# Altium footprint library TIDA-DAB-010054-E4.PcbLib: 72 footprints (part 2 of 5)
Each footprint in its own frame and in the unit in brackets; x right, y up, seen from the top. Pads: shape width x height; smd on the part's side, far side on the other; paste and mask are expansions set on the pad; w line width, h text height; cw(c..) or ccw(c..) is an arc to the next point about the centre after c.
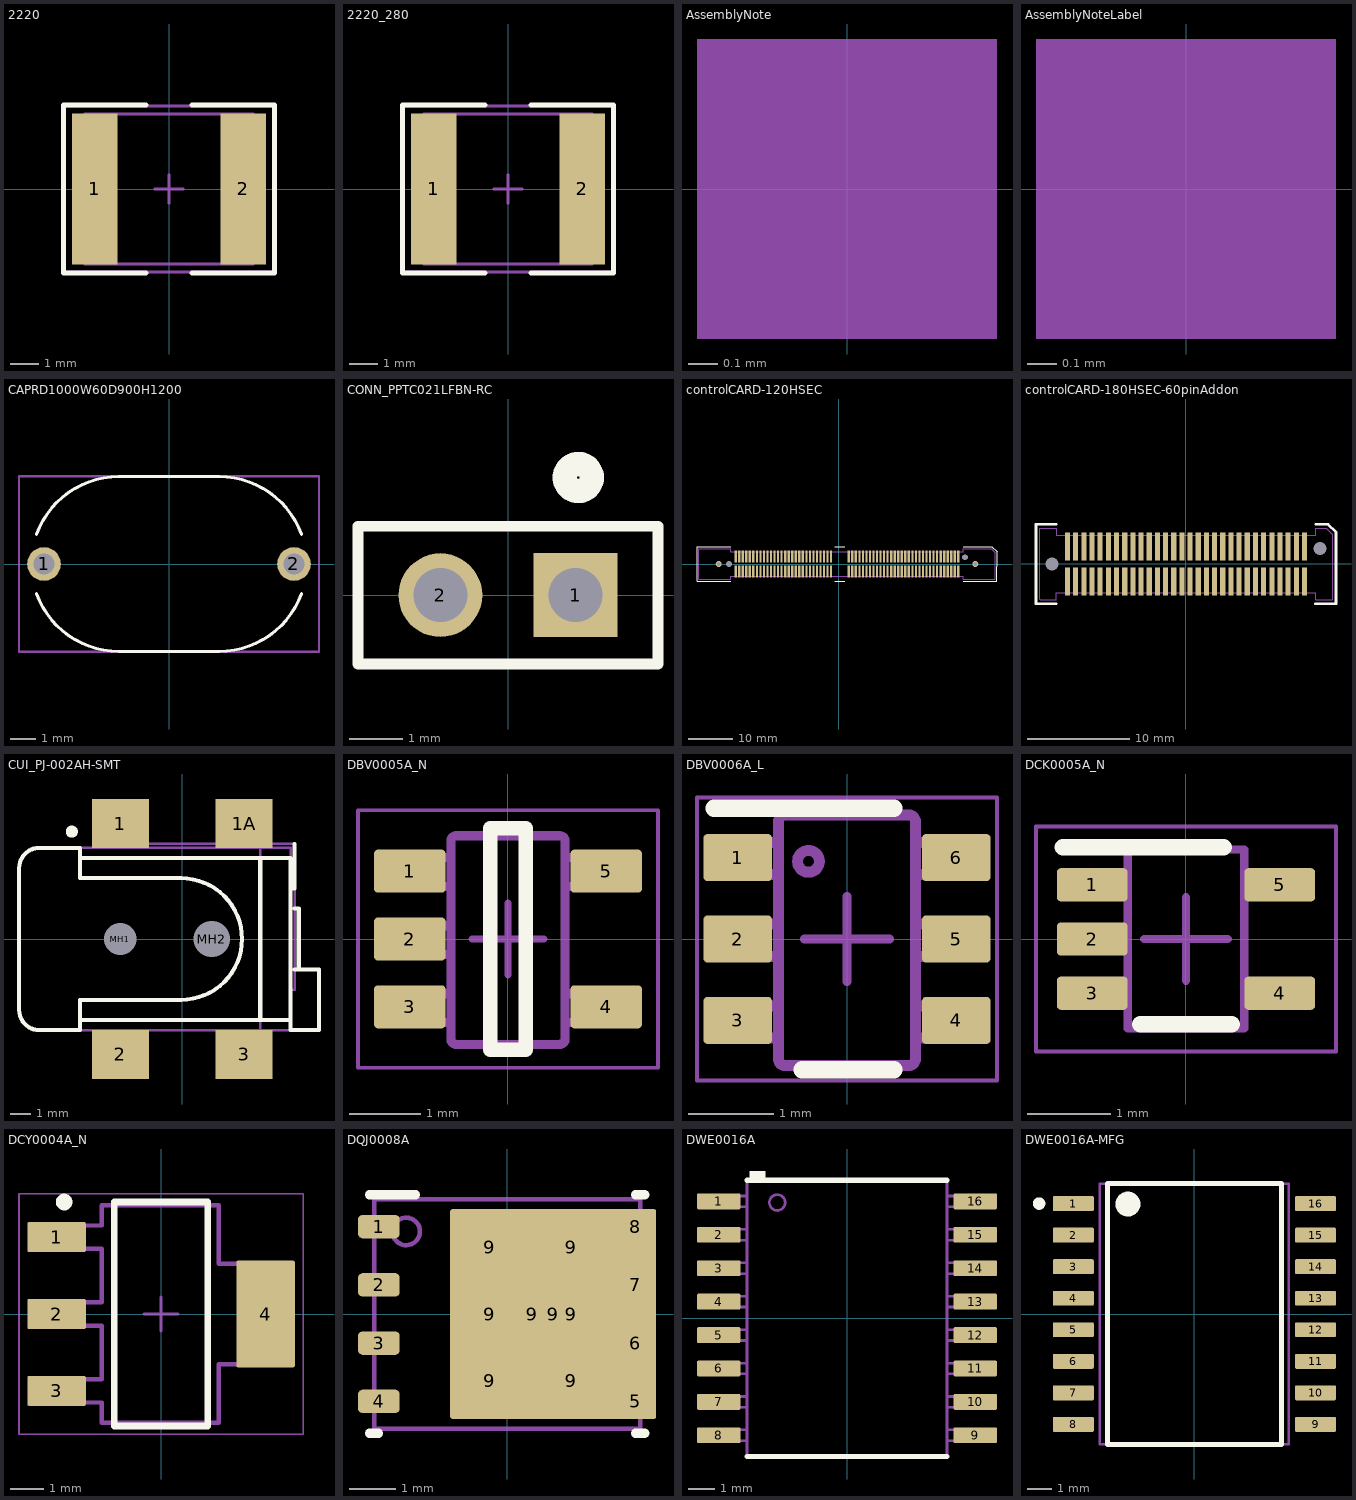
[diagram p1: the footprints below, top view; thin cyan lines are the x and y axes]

## 2220 [mm] "Chip Capacitor, Body 5.7x5.0mm, IPC Medium Density"
height 1.35
pads (2):
  rect 1.6x5.3 smd: 1(-2.6,0) 2(2.6,0)
Top Overlay:
  lines w0.178: -0.811,-2.939 -3.693,-2.939 -3.693,2.939 -0.811,2.939 ; 0.811,-2.939 3.693,-2.939 3.693,2.939 0.811,2.939
Mechanical 5:
  lines w0.1: -2.95,-2.625 2.95,-2.625 2.95,2.625 -2.95,2.625 -2.95,-2.625
  text ".Designator" at 0.508,0.378 h0.51
Mechanical 13:
  lines w0.1: -2.75,-2.625 -2.75,2.625 ; 2.75,-2.625 2.75,2.625 ; -2.95,-2.625 -2.95,2.625 2.95,2.625 2.95,-2.625 -2.95,-2.625
Mechanical 15:
  lines w0.1: -0.5,0 0.5,0 ; 0,-0.5 0,0.5 ; -3.65,-2.9 -3.65,2.9 3.65,2.9 3.65,-2.9 -3.65,-2.9
3D body: height 1.35, standoff 0, extent -2.949,-2.624 -2.751,2.624
3D body: height 1.35, standoff 0, extent -2.749,-2.624 2.749,2.624
3D body: height 1.35, standoff 0, extent 2.751,-2.624 2.949,2.624

## 2220_280 [mm] "Chip Capacitor, Body 5.7x5.0mm, IPC Medium Density"
height 2.8
pads (2):
  rect 1.6x5.3 smd: 1(-2.6,0) 2(2.6,0)
Top Overlay:
  lines w0.178: -0.811,-2.939 -3.693,-2.939 -3.693,2.939 -0.811,2.939 ; 0.811,-2.939 3.693,-2.939 3.693,2.939 0.811,2.939
Mechanical 5:
  lines w0.1: -2.95,-2.625 2.95,-2.625 2.95,2.625 -2.95,2.625 -2.95,-2.625
  text ".Designator" at 0.599,0.378 h0.51
Mechanical 13:
  lines w0.1: -2.75,-2.625 -2.75,2.625 ; 2.75,-2.625 2.75,2.625 ; -2.95,-2.625 -2.95,2.625 2.95,2.625 2.95,-2.625 -2.95,-2.625
Mechanical 15:
  lines w0.1: -0.5,0 0.5,0 ; 0,-0.5 0,0.5 ; -3.65,-2.9 -3.65,2.9 3.65,2.9 3.65,-2.9 -3.65,-2.9
3D body: height 2.8, standoff 0, extent -2.949,-2.624 -2.751,2.624
3D body: height 2.8, standoff 0, extent -2.749,-2.624 2.749,2.624
3D body: height 2.8, standoff 0, extent 2.751,-2.624 2.949,2.624

## AssemblyNote [mm] "Assembly Note"
Mechanical 5:
  rectangle: -0.508,-0.508 0.508,0.508
  text ".Comment" at 1.143,-0.508 h0.51
  text ".Designator" at -4.191,-0.508 h0.51

## AssemblyNoteLabel [mm] "Assembly Note for PCB Labels"
Mechanical 5:
  rectangle: -0.508,-0.508 0.508,0.508
  text ".Designator" at -4.191,-0.508 h0.51
  text "Install label in silkscreened box after final wash.  Text shall be 8 pt font.  Text shall be per the Label Table in the PDF schematic." at 1.143,-0.508 h0.51

## CAPRD1000W60D900H1200 [mm] "Disk, Radial Capacitor"
height 12.5
pads (2):
  round 1.35 hole 0.85: 1(-5,0) 2(5,0)
Top Overlay:
  lines w0.127: -5.296,-1.192 ccw(c-2.007,0.005) -2.007,-3.495 ; -5.296,1.192 cw(c-2.007,-0.005) -2.007,3.495 ; -2,-3.5 2.007,-3.5 ; -2,3.5 2,3.5 ; 2.007,-3.495 ccw(c2.007,0.005) 5.296,-1.192 ; 2.007,3.495 cw(c2.007,-0.005) 5.296,1.192
Mechanical 5:
  lines w0.1: -6,-3.5 6,-3.5 6,3.5 -6,3.5 -6,-3.5
  text ".Designator" at 1.205,0.068 h0.51
3D body: height 11.99, standoff 3.01, extent -4.482,-3.5 4.482,3.5

## CONN_PPTC021LFBN-RC [mil] "SULLINS"
height 335
pads (2):
  rect 62x62 hole 40: 1(50,0)
  round 62 hole 40.16: 2(-50,0)
Top Overlay:
  circle w18: c52,87 r10
  lines w8: -111,-51 -111,51 111,51 111,-51 -111,-51
Mechanical 5:
  lines w3: -110,-50 110,-50 110,50 -110,50 -110,-50
  text ".Designator" at -6.76,26.23 h20
3D body: height 130, standoff -126, extent 34,-9 66,9
3D body: height 130, standoff -126, extent -66,-9 -34,9
3D body: height 335, standoff 0, extent -109.98,-49.98 109.98,49.98
3D body: height 336, standoff 334, extent 30,-20 70,20
3D body: height 336, standoff 334, extent -70,-20 -30,20

## controlCARD-120HSEC [mm] "Pads are not numbered according to Samtec datasheet."
height 7.13
pads (124):
  rect 0.5x2.724 smd: 1(-23.357,-1.678) 2(-23.357,1.722) 3(-22.557,-1.678) 4(-22.557,1.722) 5(-21.757,-1.678) 6(-21.757,1.722) 7(-20.957,-1.678) 8(-20.957,1.722) 9(-20.157,-1.678) 10(-20.157,1.722) 11(-19.357,-1.678) 12(-19.357,1.722) 13(-18.557,-1.678) 14(-18.557,1.722) 15(-17.757,-1.678) 16(-17.757,1.722) 17(-16.957,-1.678) 18(-16.957,1.722) 19(-16.157,-1.678) 20(-16.157,1.722) 21(-15.357,-1.678) 22(-15.357,1.722) 23(-14.557,-1.678) 24(-14.557,1.722) 25(-13.757,-1.678) 26(-13.757,1.722) 27(-12.957,-1.678) 28(-12.957,1.722) 29(-12.157,-1.678) 30(-12.157,1.722) 31(-11.357,-1.678) 32(-11.357,1.722) 33(-10.557,-1.678) 34(-10.557,1.722) 35(-9.757,-1.678) 36(-9.757,1.722) 37(-8.957,-1.678) 38(-8.957,1.722) 39(-8.157,-1.678) 40(-8.157,1.722) 41(-7.357,-1.678) 42(-7.357,1.722) 43(-6.557,-1.678) 44(-6.557,1.722) 45(-5.757,-1.678) 46(-5.757,1.722) 47(-4.957,-1.678) 48(-4.957,1.722) 49(-4.157,-1.678) 50(-4.157,1.722) 51(-3.357,-1.678) 52(-3.357,1.722) 53(-2.557,-1.678) 54(-2.557,1.722) 55(-1.757,-1.678) 56(-1.757,1.722) 57(2.243,-1.678) 58(2.243,1.722) 59(3.043,-1.678) 60(3.043,1.722) 61(3.843,-1.678) 62(3.843,1.722) 63(4.643,-1.678) 64(4.643,1.722) 65(5.443,-1.678) 66(5.443,1.722) 67(6.243,-1.678) 68(6.243,1.722) 69(7.043,-1.678) 70(7.043,1.722) 71(7.843,-1.678) 72(7.843,1.722) 73(8.643,-1.678) 74(8.643,1.722) 75(9.443,-1.678) 76(9.443,1.722) 77(10.243,-1.678) 78(10.243,1.722) 79(11.043,-1.678) 80(11.043,1.722) 81(11.843,-1.678) 82(11.843,1.722) 83(12.643,-1.678) 84(12.643,1.722) 85(13.443,-1.678) 86(13.443,1.722) 87(14.243,-1.678) 88(14.243,1.722) 89(15.043,-1.678) 90(15.043,1.722) 91(15.843,-1.678) 92(15.843,1.722) 93(16.643,-1.678) 94(16.643,1.722) 95(17.443,-1.678) 96(17.443,1.722) 97(18.243,-1.678) 98(18.243,1.722) 99(19.043,-1.678) 100(19.043,1.722) 101(19.843,-1.678) 102(19.843,1.722) 103(20.643,-1.678) 104(20.643,1.722) 105(21.443,-1.678) 106(21.443,1.722) 107(22.243,-1.678) 108(22.243,1.722) 109(23.043,-1.678) 110(23.043,1.722) 111(23.843,-1.678) 112(23.843,1.722) 113(24.643,-1.678) 114(24.643,1.722) 115(25.443,-1.678) 116(25.443,1.722) 117(26.243,-1.678) 118(26.243,1.722) 119(27.043,-1.678) 120(27.043,1.722)
  round 0.025 hole 1.27 unplated mask+0.876: 181(-24.857,0.022) 182(28.543,1.522)
  round 1.348 hole 0.84: 185(-27.207,0.022) 186(30.893,0.022)
Top Overlay:
  lines w0.254: -24.457,-3.859 -32.113,-3.859 -32.113,3.903 -24.457,3.903 ; -0.876,-3.859 1.362,-3.859 ; -0.876,3.903 1.362,3.903 ; 28.143,-3.859 35.799,-3.859 35.799,2.76 34.656,3.903 28.143,3.903
Mechanical 5:
  lines w0.1: -31.732,-3.478 -31.732,3.522 -24.457,3.522 -24.457,2.822 28.143,2.822 28.143,3.522 34.443,3.522 35.418,2.547 35.418,-3.478 28.143,-3.478 28.143,-2.778 -24.457,-2.778 -24.457,-3.478 -31.732,-3.478
  text ".Designator" at -0.213,0.086 h0.51
3D body "Samtec-HSEC8-160-01-L-DV-A-BL.stp": height 12.35, standoff -1.35, extent -31.75,-3.475 35.3,3.525

## controlCARD-180HSEC-60pinAddon [mm] "Pads are not numbered according to datasheet."
height 7.13
pads (62):
  round 0.025 hole 1.27 unplated mask+0.876: 61(-13.1,0) 62(13.1,1.5)
  rect 0.5x2.724 smd: 121(-11.6,-1.7) 122(-11.6,1.7) 123(-10.8,-1.7) 124(-10.8,1.7) 125(-10,-1.7) 126(-10,1.7) 127(-9.2,-1.7) 128(-9.2,1.7) 129(-8.4,-1.7) 130(-8.4,1.7) 131(-7.6,-1.7) 132(-7.6,1.7) 133(-6.8,-1.7) 134(-6.8,1.7) 135(-6,-1.7) 136(-6,1.7) 137(-5.2,-1.7) 138(-5.2,1.7) 139(-4.4,-1.7) 140(-4.4,1.7) 141(-3.6,-1.7) 142(-3.6,1.7) 143(-2.8,-1.7) 144(-2.8,1.7) 145(-2,-1.7) 146(-2,1.7) 147(-1.2,-1.7) 148(-1.2,1.7) 149(-0.4,-1.7) 150(-0.4,1.7) 151(0.4,-1.7) 152(0.4,1.7) 153(1.2,-1.7) 154(1.2,1.7) 155(2,-1.7) 156(2,1.7) 157(2.8,-1.7) 158(2.8,1.7) 159(3.6,-1.7) 160(3.6,1.7) 161(4.4,-1.7) 162(4.4,1.7) 163(5.2,-1.7) 164(5.2,1.7) 165(6,-1.7) 166(6,1.7) 167(6.8,-1.7) 168(6.8,1.7) 169(7.6,-1.7) 170(7.6,1.7) 171(8.4,-1.7) 172(8.4,1.7) 173(9.2,-1.7) 174(9.2,1.7) 175(10,-1.7) 176(10,1.7) 177(10.8,-1.7) 178(10.8,1.7) 179(11.6,-1.7) 180(11.6,1.7)
Top Overlay:
  lines w0.254: -12.7,-3.881 -14.681,-3.881 -14.681,3.881 -12.7,3.881 ; 12.665,-3.881 14.681,-3.881 14.681,3.119 13.919,3.881 12.69,3.881
Mechanical 5:
  lines w0.1: -14.3,-3.468 -14.3,3.5 -12.7,3.5 -12.7,2.8 12.7,2.8 12.7,3.5 13.732,3.5 14.3,2.932 14.3,-3.5 12.7,-3.5 12.7,-2.8 -12.7,-2.8 -12.7,-3.5 -14.268,-3.5 -14.3,-3.468
  text ".Designator" at 0.059,0.167 h0.51
3D body "HSEC8-130-01-L-DV-A.stp": height 7.95, standoff -1.35, extent -14.3,-3.5 14.3,3.5

## CUI_PJ-002AH-SMT [mm] "CUI"
height 11.2
pads (6):
  rect 2.8x2.4 smd: 1(-3.05,5.7) 1A(3.05,5.7) 2(-3.05,-5.7) 3(3.05,-5.7)
  round 1 hole 1.6 unplated: MH1(-3.05,0)
  round 1.524 hole 1.8 unplated: MH2(1.45,0)
Top Overlay:
  circle w0.3: c-5.45,5.3 r0.15
  lines w0.2: -7.782,4.181 cw(c-7.048,3.497) -7.467,4.409 ; -7.467,-4.409 ccw(c-7.05,-3.5) -7.337,-4.458 ccw(c-7.048,-3.492) -7.185,-4.491 ccw(c-7.05,-3.5) -7.05,-4.5 -5.05,-4.5 -5.05,-4.3 -5.05,-3 -0.05,-3 ccw(c-0.05,0) 2.95,0 ccw(c-0.05,0) -0.05,3 -5.05,3 -5.05,4.3 -5.05,4.5 -7.05,4.5 ccw(c-7.05,3.5) -7.165,4.493 ccw(c-7.048,3.491) -7.36,4.451 ccw(c-7.05,3.5) -7.426,4.427 ccw(c-7.048,3.498) -7.786,4.176 ccw(c-7.05,3.5) -8.05,3.5 -8.05,-3.5 ccw(c-7.05,-3.5) -7.782,-4.181 ccw(c-7.048,-3.498) -7.467,-4.409 ; -7.336,4.458 cw(c-7.048,3.492) -7.185,4.491 ; -5.05,-4 3.85,-4 ; -5.05,4 3.85,4 ; 5.35,2.5 5.55,2.5 5.55,4.7 ; 5.55,-1.5 5.75,-1.5 ; 5.55,1.5 5.75,1.5 5.75,-1.5 ; 3.85,-4 3.85,4 ; 3.85,-4 5.35,-4 ; 3.85,-4 3.85,4 ; 3.85,4 5.35,4 5.35,-4 ; 5.35,-4 5.35,-4.5 6.75,-4.5 6.75,-1.5 5.75,-1.5 ; -7.786,-4.176 ccw(c-7.049,-3.499) -7.426,-4.427 cw(c-7.05,-3.5) -7.786,-4.177 ; -7.36,-4.451 ccw(c-7.048,-3.491) -7.165,-4.493 cw(c-7.05,-3.5) -7.36,-4.451
Mechanical 5:
  lines w0.127: -7.782,4.181 cw(c-7.048,3.497) -7.467,4.409 ; -7.467,-4.409 ccw(c-7.05,-3.5) -7.337,-4.458 ccw(c-7.048,-3.492) -7.185,-4.491 ccw(c-7.05,-3.5) -7.05,-4.5 -5.05,-4.5 ; -7.467,-4.409 cw(c-7.048,-3.498) -7.782,-4.181 cw(c-7.05,-3.5) -8.05,-3.5 -8.05,3.5 cw(c-7.05,3.5) -7.786,4.177 cw(c-7.048,3.498) -7.426,4.427 cw(c-7.05,3.5) -7.36,4.451 cw(c-7.048,3.491) -7.165,4.493 cw(c-7.05,3.5) -7.05,4.5 -5.05,4.5 ; -7.336,4.458 cw(c-7.048,3.492) -7.185,4.491 ; -5.05,-4 3.85,-4 ; -5.05,4 3.85,4 ; -4.4,4.5 -4.4,5 -3.1,5 -3.1,4.5 ; -3.8,-4.5 -3.8,-5 ; -3.8,5 -3.8,6.3 -2.3,6.3 -2.3,4.7 ; -3.1,4.7 5.55,4.7 5.55,2.5 ; -2.3,-4.5 -2.3,-5 ; 1.8,-4.5 1.8,-5 3.8,-5 ; 2.3,-5 2.3,-6.3 3.8,-6.3 3.8,-5 ; 2.3,4.7 2.3,6.3 3.8,6.3 3.8,4.7 ; 3.8,-4.5 3.8,-5 ; 5.35,-2.5 5.55,-2.5 5.55,2.5 ; 5.35,2.5 5.55,2.5 ; 5.55,-1.5 5.75,-1.5 ; 5.55,1.5 5.75,1.5 5.75,-1.5 ; -5.05,-4.5 -5.05,-4.3 -5.05,-3 -0.05,-3 ccw(c-0.05,0) 2.95,0 ccw(c-0.05,0) -0.05,3 -5.05,3 -5.05,4.3 -5.05,4.5 ; -5.05,-4.5 3.85,-4.5 ; -5.05,4.5 3.85,4.5 ; -3.8,-5 -2.3,-5 ; -3.8,-5 -3.8,-6.3 -2.3,-6.3 -2.3,-5 ; 3.85,-4.5 5.35,-4.5 ; 3.85,-4.5 3.85,-4 ; 3.85,-4.5 3.85,-4 ; 3.85,-4 3.85,4 ; 3.85,-4 5.35,-4 ; 3.85,-4 3.85,4 ; 3.85,4 5.35,4 ; 3.85,4 3.85,4.5 ; 3.85,4 3.85,4.5 ; 3.85,4.5 5.35,4.5 5.35,4 ; 5.35,-4.5 5.35,-4 ; 5.35,-4.5 6.75,-4.5 6.75,-1.5 5.75,-1.5 ; 5.35,-4 5.35,4 ; -7.786,-4.177 ccw(c-7.05,-3.5) -7.426,-4.427 cw(c-7.049,-3.499) -7.786,-4.176 ; -7.36,-4.451 ccw(c-7.05,-3.5) -7.165,-4.493 cw(c-7.048,-3.491) -7.36,-4.451
  text ".Designator" at -1.8,-0.45 h0.51
3D body "CUI_PJ-002AH-SMT-TR.stp": height 11.2, standoff -1, extent -8.05,-6.3 6.75,6.3

## DBV0005A_N [mm] "SOT23, 5-Leads, Body 2.9x1.6mm, Pitch 0.95mm, Lead Span 2.8mm, IPC Medium Density"
height 1.45
pads (5):
  rrect17% 1x0.6 smd: 1(-1.375,0.95) 2(-1.375,0) 3(-1.375,-0.95) 4(1.375,-0.95) 5(1.375,0.95)
Top Overlay:
  lines w0.2: -0.25,-1.55 -0.25,1.55 0.25,1.55 0.25,-1.55 -0.25,-1.55
Mechanical 5:
  lines w0.127: -0.801,1.371 cw(c-0.725,1.37) -0.725,1.446 ; -0.801,1.37 -0.801,1.371 ; -0.801,1.37 -0.801,-1.399 -0.801,-1.4 ccw(c-0.725,-1.399) -0.725,-1.475 ; -0.725,-1.475 0.723,-1.475 0.724,-1.475 ccw(c0.723,-1.399) 0.799,-1.4 0.799,-1.399 0.799,1.37 ; -0.725,-1.475 -0.725,-1.475 ; -0.725,1.446 -0.725,1.446 ; -0.725,1.446 0.723,1.446 0.724,1.446 cw(c0.723,1.37) 0.799,1.371 ; 0.799,1.37 0.799,1.371 ; -1.423,-1.167 -1.423,-0.767 -1.199,-0.767 -1.105,-0.767 -1.088,-0.767 -0.835,-0.767 -0.801,-0.767 -0.801,-1.167 -0.835,-1.167 -1.088,-1.167 -1.105,-1.167 -1.199,-1.167 -1.423,-1.167 ; -1.423,-0.215 -1.423,0.186 -1.199,0.186 -1.105,0.186 -1.088,0.186 -0.835,0.186 -0.801,0.186 -0.801,-0.215 -0.835,-0.215 -1.088,-0.215 -1.105,-0.215 -1.199,-0.215 -1.423,-0.215 ; -1.423,0.738 -1.423,1.138 -1.199,1.138 -1.105,1.138 -1.088,1.138 -0.835,1.138 -0.801,1.138 -0.801,0.738 -0.835,0.738 -1.088,0.738 -1.105,0.738 -1.199,0.738 -1.423,0.738 ; 0.799,-1.167 0.834,-1.167 1.087,-1.167 1.103,-1.167 1.198,-1.167 1.422,-1.167 1.422,-0.767 1.198,-0.767 1.103,-0.767 1.087,-0.767 0.834,-0.767 0.799,-0.767 0.799,-1.167 ; 0.799,0.738 0.834,0.738 1.087,0.738 1.103,0.738 1.198,0.738 1.422,0.738 1.422,1.138 1.198,1.138 1.103,1.138 1.087,1.138 0.834,1.138 0.799,1.138 0.799,0.738
  text ".Designator" at -0.25,0.77 h0.51
Mechanical 15:
  lines w0.05: -2.1,-1.8 -2.1,1.8 2.1,1.8 2.1,-1.8 -2.1,-1.8
  lines w0.1: -0.5,0 0.5,0 ; 0,-0.5 0,0.5
3D body "DBV0005A.stp": height 1.09, standoff 0, extent -1.422,-1.461 1.423,1.46

## DBV0006A_L [mm] "SOT23, 6-Leads, Body 2.9x1.6mm, Pitch 0.95mm, Lead Span 2.8mm, IPC High Density"
height 1.45
pads (6):
  rrect18% 0.8x0.55 smd: 1(-1.275,0.95) 2(-1.275,0) 3(-1.275,-0.95) 4(1.275,-0.95) 5(1.275,0) 6(1.275,0.95)
Top Overlay:
  lines w0.2: -1.55,1.525 0.55,1.525 ; -0.525,-1.525 0.55,-1.525
Mechanical 5:
  lines w0.127: 0.724,-1.475 ccw(c0.723,-1.399) 0.8,-1.399 0.8,1.37 ccw(c0.723,1.37) 0.724,1.446 ; 0.723,-1.475 0.724,-1.475 ; 0.723,-1.475 -0.724,-1.475 -0.725,-1.475 cw(c-0.724,-1.399) -0.801,-1.399 -0.801,1.37 cw(c-0.724,1.37) -0.725,1.446 -0.724,1.446 0.723,1.446 ; 0.723,1.446 0.724,1.446 ; -1.423,-1.154 -1.206,-1.154 -1.113,-1.154 -1.081,-1.154 -0.828,-1.154 -0.801,-1.154 -0.801,-0.78 -0.828,-0.78 -1.081,-0.78 -1.113,-0.78 -1.206,-0.78 -1.423,-0.78 -1.423,-1.154 ; -1.423,-0.202 -1.206,-0.202 -1.113,-0.202 -1.081,-0.202 -0.828,-0.202 -0.801,-0.202 -0.801,0.173 -0.828,0.173 -1.081,0.173 -1.113,0.173 -1.206,0.173 -1.423,0.173 -1.423,-0.202 ; -1.423,0.751 -1.206,0.751 -1.113,0.751 -1.081,0.751 -0.828,0.751 -0.801,0.751 -0.801,1.125 -0.828,1.125 -1.081,1.125 -1.113,1.125 -1.206,1.125 -1.423,1.125 -1.423,0.751 ; -0.577,0.906 cw(c-0.45,0.906) -0.323,0.906 cw(c-0.45,0.906) -0.577,0.906 ; 0.8,-1.154 0.827,-1.154 1.08,-1.154 1.112,-1.154 1.205,-1.154 1.422,-1.154 1.422,-0.78 1.205,-0.78 1.112,-0.78 1.08,-0.78 0.827,-0.78 0.8,-0.78 0.8,-1.154 ; 0.8,-0.202 0.827,-0.202 1.08,-0.202 1.112,-0.202 1.205,-0.202 1.422,-0.202 1.422,0.173 1.205,0.173 1.112,0.173 1.08,0.173 0.827,0.173 0.8,0.173 0.8,-0.202 ; 0.8,0.751 0.827,0.751 1.08,0.751 1.112,0.751 1.205,0.751 1.422,0.751 1.422,1.125 1.205,1.125 1.112,1.125 1.08,1.125 0.827,1.125 0.8,1.125 0.8,0.751
  text ".Designator" at -0.236,0.395 h0.51
Mechanical 15:
  lines w0.05: -1.75,-1.65 1.75,-1.65 1.75,1.65 -1.75,1.65 -1.75,-1.65
  lines w0.1: -0.5,0 0.5,0 ; 0,-0.5 0,0.5
3D body "DBV0006A.stp": height 1.12, standoff 0, extent -1.422,-1.461 1.423,1.46

## DCK0005A_N [mm] "SOT353, 5-Leads, Body 2x1.3mm, Pitch 0.65mm, Lead Span 2.1mm, IPC Medium Density"
height 1.1
pads (5):
  rrect25% 0.85x0.4 smd: 1(-1.125,0.65) 2(-1.125,0) 3(-1.125,-0.65) 4(1.125,-0.65) 5(1.125,0.65)
Top Overlay:
  lines w0.2: -1.475,1.1 0.45,1.1 ; -0.55,-1.025 0.55,-1.025
Mechanical 5:
  lines w0.1: -0.7,-1.075 -0.7,1.075 0.7,1.075 0.7,-1.075 -0.7,-1.075
  lines w0.127: -0.865,0.762 -0.853,0.762 ; -0.711,-0.763 -0.853,-0.763 -0.865,-0.763 -0.959,-0.763 -1.143,-0.763 -1.143,-0.538 -0.959,-0.538 -0.865,-0.538 -0.853,-0.538 -0.711,-0.538 ; -0.711,-0.113 -0.853,-0.113 -0.865,-0.113 -0.959,-0.113 -1.143,-0.113 -1.143,0.112 -0.959,0.112 -0.865,0.112 -0.853,0.112 -0.711,0.112 ; -0.711,0.537 -0.853,0.537 -0.865,0.537 -0.959,0.537 -1.143,0.537 -1.143,0.762 -0.959,0.762 -0.711,0.762 ; 0.711,-0.763 0.847,-0.763 0.859,-0.763 0.953,-0.763 1.137,-0.763 1.137,-0.538 0.953,-0.538 0.859,-0.538 0.847,-0.538 0.711,-0.538 ; 0.711,0.537 0.847,0.537 0.859,0.537 0.953,0.537 1.137,0.537 1.137,0.762 0.953,0.762 0.859,0.762 0.847,0.762 0.711,0.762
  text ".Designator" at -0.246,0.748 h0.51
Mechanical 15:
  lines w0.05: -1.8,-1.35 -1.8,1.35 1.8,1.35 1.8,-1.35 -1.8,-1.35
  lines w0.1: -0.5,0 0.5,0 ; 0,-0.5 0,0.5
3D body "DCK0005A.stp": height 0.95, standoff 0, extent -1.14,-1 1.14,1

## DCY0004A_N [mm] "SOT223/SC73, 4-Leads, Body 6.5x3.5mm, Pitch 2.3mm, Lead Span 7mm, IPC Medium Density"
height 1.8
pads (4):
  rrect11% 1.75x0.9 smd: 1(-3.125,2.3) 2(-3.125,0) 3(-3.125,-2.3)
  rrect6% 1.75x3.2 smd: 4(3.125,0)
Top Overlay:
  circle w0.25: c-2.9,3.35 r0.125
  lines w0.2: -1.4,-3.35 1.4,-3.35 1.4,3.35 -1.4,3.35 -1.4,-3.35
Mechanical 5:
  lines w0.127: -3.525,-2.65 -2.797,-2.65 -2.612,-2.65 -2.374,-2.65 -2.003,-2.65 -1.775,-2.65 -1.775,-3.25 1.725,-3.25 1.725,-1.5 1.953,-1.5 2.324,-1.5 2.562,-1.5 2.747,-1.5 3.475,-1.5 3.475,1.5 2.747,1.5 2.562,1.5 2.324,1.5 1.953,1.5 1.725,1.5 1.725,3.25 -1.775,3.25 -1.775,2.65 -2.003,2.65 -2.374,2.65 -2.612,2.65 -2.797,2.65 -3.525,2.65 -3.525,1.95 -2.797,1.95 -2.612,1.95 -2.374,1.95 -2.003,1.95 -1.775,1.95 -1.775,0.35 -2.003,0.35 -2.374,0.35 -2.612,0.35 -2.797,0.35 -3.525,0.35 -3.525,-0.35 -2.797,-0.35 -2.612,-0.35 -2.374,-0.35 -2.003,-0.35 -1.775,-0.35 -1.775,-1.95 -2.003,-1.95 -2.374,-1.95 -2.612,-1.95 -2.797,-1.95 -3.525,-1.95 -3.525,-2.65
  text ".Designator" at 0.19,-0.449 h0.51
Mechanical 15:
  lines w0.05: -4.25,-3.6 -4.25,3.6 4.25,3.6 4.25,-3.6 -4.25,-3.6
  lines w0.1: -0.5,0 0.5,0 ; 0,-0.5 0,0.5
3D body "DCY0004A.stp": height 1.68, standoff 0, extent -3.48,-3.25 3.48,3.25

## DQJ0008A [mm] "SMD, 8-Leads, Body 5.75x4.9mm"
height 1.1
pads (16):
  rrect39% 0.91x0.51 smd paste-0.05 mask-0.05: 1(-2.795,1.905) 2(-2.795,0.635) 3(-2.795,-0.635) 4(-2.795,-1.905) 5(2.795,-1.905) 6(2.795,-0.635) 7(2.795,0.635) 8(2.795,1.905)
  rrect50% 1.58x1.25 on Top Paste: 9(-0.38,-1.45) 9(-0.38,0) 9(-0.38,1.45) 9(1.4,-1.45) 9(1.4,0) 9(1.4,1.45)
  rrect50% 3.48x4.47 on Top Solder: 9(0.55,0)
  rrect2% 4.49x4.57 smd paste-2.5 mask-2.5: 9(1.005,0)
Top Overlay:
  lines w0.2: -3,-2.6 -2.8,-2.6 ; -3,2.6 -2,2.6 ; 2.8,-2.6 3,-2.6 ; 2.8,2.6 3,2.6
Top Solder:
  rectangle: 2.25,-0.84 2.475,-0.43
  rectangle: 2.25,-2.11 2.475,-1.7
  rectangle: 2.25,1.7 2.475,2.11
  rectangle: 2.25,0.43 2.475,0.84
Mechanical 5:
  circle w0.1: c-2.2,1.8 r0.3
  lines w0.1: -2.9,-2.5 -2.9,2.5 2.9,2.5 2.9,-2.5 -2.9,-2.5
  text ".Designator" at -0.127,0.561 h0.51
3D body "DQJ0008A.stp": height 1.15, standoff 0, extent -3.13,-2.45 3.13,2.45

## DWE0016A [mm] "SOIC, 16-Leads, Body 10.5x7.6mm, Pitch 1.27mm"
height 2.65
pads (16):
  rrect17% 1.65x0.6 smd: 1(-4.875,4.445) 2(-4.875,3.175) 3(-4.875,1.905) 4(-4.875,0.635) 5(-4.875,-0.635) 6(-4.875,-1.905) 7(-4.875,-3.175) 8(-4.875,-4.445) 9(4.875,-4.445) 10(4.875,-3.175) 11(4.875,-1.905) 12(4.875,-0.635) 13(4.875,0.635) 14(4.875,1.905) 15(4.875,3.175) 16(4.875,4.445)
Top Overlay:
  rectangle: -3.7,5.35 -3.1,5.6
  lines w0.2: -3.8,-5.25 3.8,-5.25 ; -3.8,5.25 3.8,5.25
Mechanical 5:
  circle w0.1: c-2.65,4.4 r0.3
  lines w0.1: -3.8,-4.65 -5.3,-4.65 -5.3,-4.24 -3.8,-4.24 ; -3.8,-3.38 -5.3,-3.38 -5.3,-2.97 -3.8,-2.97 ; -3.8,-2.11 -5.3,-2.11 -5.3,-1.7 -3.8,-1.7 ; -3.8,-0.84 -5.3,-0.84 -5.3,-0.43 -3.8,-0.43 ; -3.8,0.43 -5.3,0.43 -5.3,0.84 -3.8,0.84 ; -3.8,1.7 -5.3,1.7 -5.3,2.11 -3.8,2.11 ; -3.8,2.97 -5.3,2.97 -5.3,3.38 -3.8,3.38 ; -3.8,4.24 -5.3,4.24 -5.3,4.65 -3.8,4.65 ; 3.8,-4.65 5.3,-4.65 5.3,-4.24 3.8,-4.24 ; 3.8,-3.38 5.3,-3.38 5.3,-2.97 3.8,-2.97 ; 3.8,-2.11 5.3,-2.11 5.3,-1.7 3.8,-1.7 ; 3.8,-0.84 5.3,-0.84 5.3,-0.43 3.8,-0.43 ; 3.8,0.43 5.3,0.43 5.3,0.84 3.8,0.84 ; 3.8,1.7 5.3,1.7 5.3,2.11 3.8,2.11 ; 3.8,2.97 5.3,2.97 5.3,3.38 3.8,3.38 ; 3.8,4.24 5.3,4.24 5.3,4.65 3.8,4.65 ; -3.8,-5.25 3.8,-5.25 3.8,5.25 -3.8,5.25 -3.8,-5.25
  text ".Designator" at 0.483,-5.25 h0.51
3D body "DWE0016A.stp": height 2.59, standoff 0, extent -5.167,-5.15 5.168,5.15

## DWE0016A-MFG [mm]
height 9.2
pads (16):
  rrect17% 1.65x0.6 smd paste+0 mask+0: 1(-4.875,4.445) 2(-4.875,3.175) 3(-4.875,1.905) 4(-4.875,0.635) 5(-4.875,-0.635) 6(-4.875,-1.905) 7(-4.875,-3.175) 8(-4.875,-4.445) 9(4.875,-4.445) 10(4.875,-3.175) 11(4.875,-1.905) 12(4.875,-0.635) 13(4.875,0.635) 14(4.875,1.905) 15(4.875,3.175) 16(4.875,4.445)
Top Overlay:
  circle w0.5: c-2.675,4.425 r0.25
  circle w0.25: c-6.25,4.445 r0.125
  lines w0.2: -3.5,-5.25 -3.5,5.25 3.5,5.25 3.5,-5.25 -3.5,-5.25
Mechanical 5:
  lines w0.1: -3.8,-5.25 -3.8,5.25 3.8,5.25 3.8,-5.25 -3.8,-5.25
  text ".Designator" at 0.247,-0.548 h0.51
3D body "IC_AMC3330DWE_SOICW16.STEP": height 0.25, standoff 0, extent -5.8,-5.5 5.8,5.5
